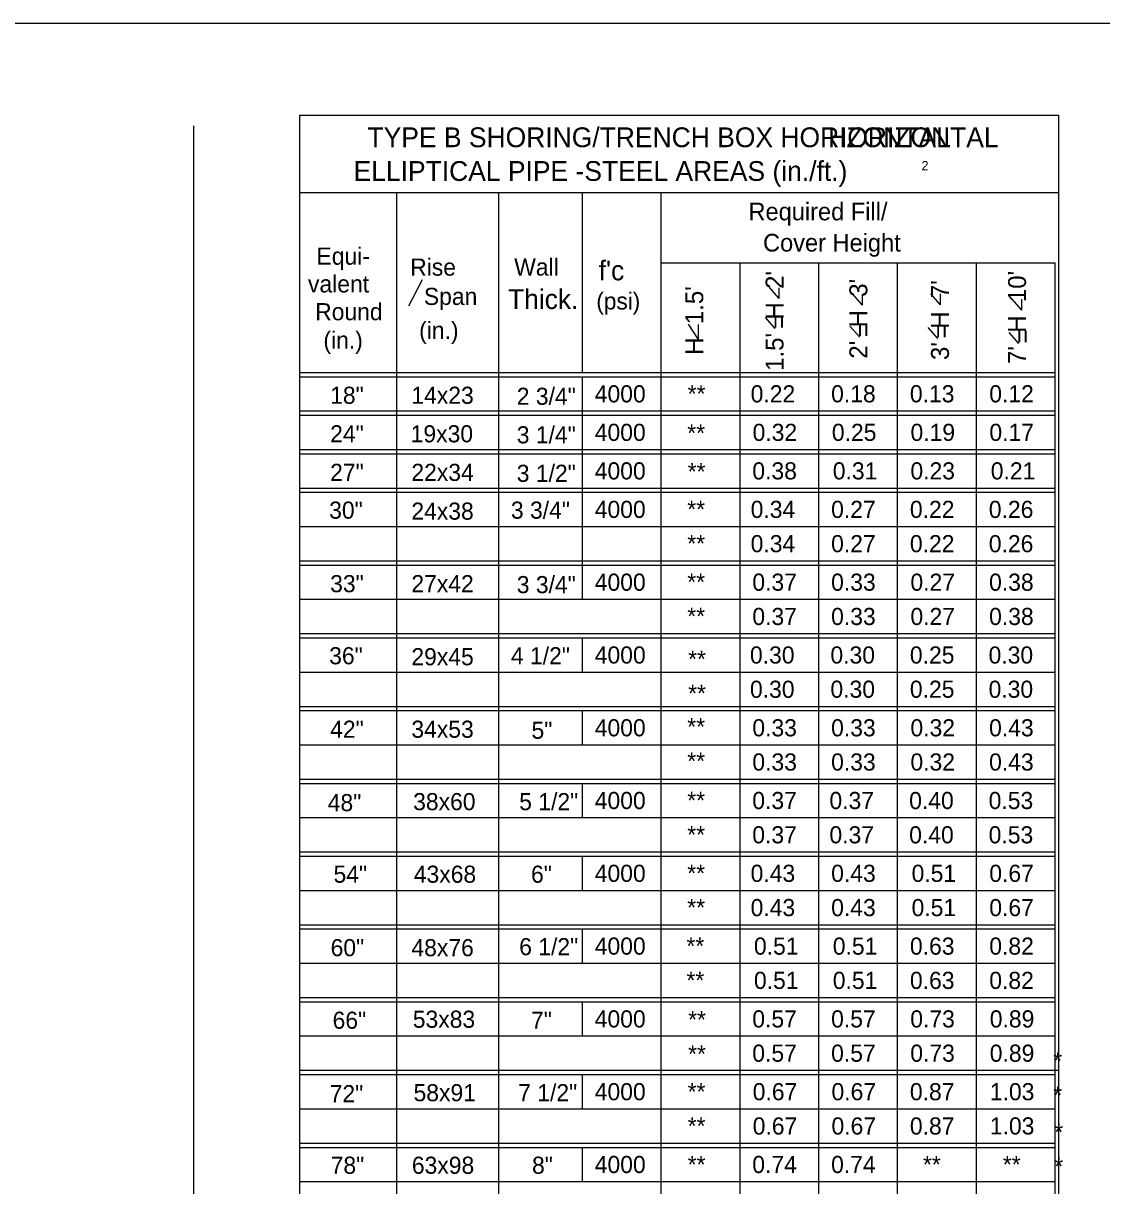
# Model space of a CAD drawing. Extents: x -22562 to -18409, y 3991 to 7171.
# Drawn here: x -19149.6 to -18976.3, y 5571.5 to 5758.4 of the extents above; entities that cross this region are included whole.
import ezdxf

# ---------------------------------------------------------------- set-up
doc = ezdxf.new("R2010")
doc.units = 0
for name, color, linetype in [('1', 7, 'Continuous'), ('2', 7, 'Continuous'), ('3', 7, 'Continuous'), ('4', 7, 'Continuous')]:
    doc.layers.add(name, color=color, linetype=linetype)

msp = doc.modelspace()

# ---------------------------------------------------------------- linework, layer by layer
at = {"layer": '1'}
for p, q in [((-19087.64, 5712.94), (-19085.45, 5717.17)), ((-19028.1, 5714.12), (-19029.67, 5715.88)), ((-19028.1, 5714.12), (-19028.1, 5715.87)), ((-19014.73, 5713.07), (-19016.29, 5714.84)), ((-19014.73, 5713.07), (-19014.73, 5714.83)), ((-19002.17, 5713.13), (-19003.73, 5714.9)), ((-19002.17, 5713.13), (-19002.17, 5714.88)), ((-18989.12, 5712.28), (-18990.68, 5714.04)), ((-18989.12, 5712.28), (-18989.12, 5714.03)), ((-19041.1, 5707.55), (-19042.67, 5709.98)), ((-19041.1, 5707.55), (-19041.1, 5709.96)), ((-19028.76, 5709.31), (-19030.32, 5711.08)), ((-19015.18, 5707.93), (-19016.75, 5709.7)), ((-19002.62, 5707.71), (-19004.18, 5709.48)), ((-18989.58, 5706.92), (-18991.14, 5708.68))]:
    msp.add_line(p, q, dxfattribs=at)
at = {"layer": '2'}
for p, q in [((-19503.85, 5758.37), (-18717.85, 5758.37)), ((-19105.2, 5743.62), (-19105.2, 5590.09)), ((-19105.2, 5743.62), (-18983.24, 5743.62)), ((-18983.23, 5743.62), (-18983.23, 5590.09)), ((-19122.26, 5741.87), (-19122.26, 5397.33)), ((-19105.2, 5731.15), (-18983.24, 5731.15)), ((-19089.62, 5731.15), (-19089.62, 5589.4)), ((-19073.24, 5731.15), (-19073.24, 5589.4)), ((-19059.78, 5731.15), (-19059.78, 5702.25)), ((-19059.77, 5731.15), (-19059.77, 5702.25)), ((-19047.12, 5731.15), (-19047.12, 5589.4)), ((-19047.12, 5719.87), (-18983.81, 5719.87)), ((-19034.45, 5719.87), (-19034.45, 5589.4)), ((-19021.79, 5719.87), (-19021.79, 5589.4)), ((-19009.13, 5719.87), (-19009.13, 5589.4)), ((-18996.46, 5719.87), (-18996.46, 5589.4)), ((-18983.81, 5719.87), (-18983.81, 5589.4)), ((-19105.2, 5702.25), (-18983.81, 5702.25)), ((-19105.2, 5701.56), (-18983.81, 5701.56)), ((-19059.77, 5701.56), (-19059.77, 5679.54)), ((-19105.2, 5696.06), (-18983.81, 5696.06)), ((-19105.2, 5696.06), (-18983.81, 5696.06)), ((-19105.2, 5695.37), (-18983.81, 5695.37)), ((-19105.2, 5695.37), (-18983.81, 5695.37)), ((-19059.77, 5695.37), (-19059.77, 5673.35)), ((-19105.2, 5689.87), (-18983.81, 5689.87)), ((-19105.2, 5689.87), (-18983.81, 5689.87)), ((-19105.2, 5689.18), (-18983.81, 5689.18)), ((-19059.77, 5689.18), (-19059.77, 5667.16)), ((-19105.2, 5683.67), (-18983.81, 5683.67)), ((-19105.2, 5683.67), (-18983.81, 5683.67)), ((-19105.2, 5683.67), (-18983.81, 5683.67)), ((-19105.2, 5682.99), (-18983.81, 5682.99)), ((-19059.77, 5682.99), (-19059.77, 5677.48)), ((-19105.2, 5677.48), (-18983.81, 5677.48)), ((-19105.2, 5671.98), (-18983.81, 5671.98)), ((-19105.2, 5671.98), (-18983.81, 5671.98)), ((-19105.2, 5671.29), (-18983.81, 5671.29)), ((-19059.77, 5671.29), (-19059.77, 5665.79)), ((-19105.2, 5665.79), (-18983.81, 5665.79)), ((-19105.2, 5660.28), (-18983.81, 5660.28)), ((-19105.2, 5660.28), (-18983.81, 5660.28)), ((-19105.2, 5659.59), (-18983.81, 5659.59)), ((-19059.77, 5659.59), (-19059.77, 5654.09)), ((-19105.2, 5654.09), (-18983.81, 5654.09)), ((-19105.2, 5648.58), (-18983.81, 5648.58)), ((-19105.2, 5648.58), (-18983.81, 5648.58)), ((-19105.2, 5647.89), (-18983.81, 5647.89)), ((-19059.77, 5647.89), (-19059.77, 5642.39)), ((-19105.2, 5642.39), (-18983.81, 5642.39)), ((-19105.2, 5636.88), (-18983.81, 5636.88)), ((-19105.2, 5636.88), (-18983.81, 5636.88)), ((-19105.2, 5636.19), (-19105.2, 5636.19)), ((-19105.2, 5636.19), (-18983.81, 5636.19)), ((-19059.77, 5636.19), (-19059.77, 5630.69)), ((-19105.2, 5630.69), (-18983.81, 5630.69)), ((-19105.2, 5625.18), (-18983.81, 5625.18)), ((-19105.2, 5625.18), (-18983.81, 5625.18)), ((-19105.2, 5624.5), (-18983.81, 5624.5)), ((-19073.24, 5624.5), (-19073.24, 5618.99)), ((-19059.77, 5624.5), (-19059.77, 5618.99)), ((-19105.2, 5618.99), (-18983.81, 5618.99)), ((-19105.2, 5613.49), (-18983.81, 5613.49)), ((-19105.2, 5613.49), (-18983.81, 5613.49)), ((-19105.2, 5612.8), (-18983.81, 5612.8)), ((-19073.24, 5612.8), (-19073.24, 5607.29)), ((-19059.77, 5612.8), (-19059.77, 5607.29)), ((-19105.2, 5607.29), (-18983.81, 5607.29)), ((-19105.2, 5601.79), (-18983.81, 5601.79)), ((-19105.2, 5601.79), (-18983.81, 5601.79)), ((-19105.2, 5601.1), (-18983.81, 5601.1)), ((-19073.24, 5601.1), (-19073.24, 5595.6)), ((-19059.77, 5601.1), (-19059.77, 5595.6)), ((-19105.2, 5595.6), (-18983.81, 5595.6)), ((-19105.2, 5590.09), (-19105.2, 5429.07)), ((-19105.2, 5590.09), (-18983.23, 5590.09)), ((-19105.2, 5590.09), (-18983.81, 5590.09)), ((-19105.2, 5590.09), (-18983.81, 5590.09)), ((-19105.2, 5589.4), (-18983.81, 5589.4)), ((-19089.62, 5589.4), (-19089.62, 5429.07)), ((-19073.24, 5589.4), (-19073.24, 5429.07)), ((-19073.24, 5589.4), (-19073.24, 5583.9)), ((-19059.77, 5589.4), (-19059.77, 5583.9)), ((-19047.12, 5589.4), (-19047.12, 5429.07)), ((-19034.45, 5589.4), (-19034.45, 5429.07)), ((-19021.79, 5589.4), (-19021.79, 5429.07)), ((-19009.13, 5589.4), (-19009.13, 5429.07)), ((-18996.46, 5589.4), (-18996.46, 5429.07)), ((-18983.81, 5589.4), (-18983.81, 5429.07)), ((-18983.23, 5590.09), (-18983.23, 5429.07)), ((-19105.2, 5583.9), (-18983.81, 5583.9)), ((-19105.2, 5578.39), (-18983.81, 5578.39)), ((-19105.2, 5578.39), (-18983.81, 5578.39)), ((-19105.2, 5577.7), (-18983.81, 5577.7)), ((-19073.24, 5577.7), (-19073.24, 5572.2)), ((-19059.77, 5577.7), (-19059.77, 5572.2)), ((-19105.2, 5572.2), (-18983.81, 5572.2))]:
    msp.add_line(p, q, dxfattribs=at)

# ---------------------------------------------------------------- texts
at = {"layer": '1'}
for s, height, p in [('HORIZONTAL', 3.178, (-19020.24, 5738.45)), ('Equi-', 2.751, (-19102.48, 5719.56)), ('Rise', 2.751, (-19087.42, 5717.8)), ('Wall', 2.751, (-19070.7, 5717.81)), ("f'c", 3.172, (-19057.13, 5717.05)), ('valent', 2.751, (-19103.84, 5715.1)), ('Span', 2.751, (-19085.22, 5713.09)), ('Thick.', 3.172, (-19071.7, 5712.44)), ('Round', 2.751, (-19102.69, 5710.63)), ('(psi)', 2.719, (-19057.51, 5712.36)), ('(in.)', 2.751, (-19085.98, 5707.64)), ('(in.)', 2.751, (-19101.37, 5706.06)), ('18"', 2.751, (-19100.28, 5697.2)), ('14x23', 2.751, (-19087.23, 5697.2)), ('2 3/4"', 2.751, (-19070.29, 5697.04)), ('24"', 2.751, (-19100.28, 5691.01)), ('19x30', 2.751, (-19087.34, 5691.01)), ('3 1/4"', 2.751, (-19070.29, 5690.85)), ('27"', 2.751, (-19100.28, 5684.81)), ('22x34', 2.751, (-19087.23, 5684.81)), ('3 1/2"', 2.751, (-19070.29, 5684.66)), ('30"', 2.751, (-19100.44, 5678.74)), ('24x38', 2.751, (-19087.23, 5678.58)), ('3 3/4"', 2.751, (-19071.23, 5678.74)), ('33"', 2.751, (-19100.28, 5666.92)), ('27x42', 2.751, (-19087.23, 5666.92)), ('3 3/4"', 2.751, (-19070.29, 5666.77)), ('36"', 2.751, (-19100.44, 5655.34)), ('29x45', 2.751, (-19087.23, 5655.18)), ('4 1/2"', 2.751, (-19071.23, 5655.34)), ('42"', 2.751, (-19100.28, 5643.53)), ('34x53', 2.751, (-19087.23, 5643.53)), ('5"', 2.751, (-19067.92, 5643.37)), ('48"', 2.751, (-19100.67, 5631.73)), ('38x60', 2.751, (-19086.94, 5631.89)), ('5 1/2"', 2.751, (-19069.9, 5631.89)), ('54"', 2.751, (-19099.74, 5620.23)), ('43x68', 2.751, (-19086.84, 5620.23)), ('6"', 2.751, (-19068, 5620.23)), ('60"', 2.751, (-19100.21, 5608.42)), ('48x76', 2.751, (-19087.22, 5608.42)), ('6 1/2"', 2.751, (-19069.9, 5608.58)), ('66"', 2.751, (-19099.89, 5596.76)), ('53x83', 2.751, (-19087, 5596.92)), ('7"', 2.751, (-19068, 5596.76)), ('72"', 2.751, (-19100.36, 5584.95)), ('58x91', 2.751, (-19086.88, 5585.11)), ('7 1/2"', 2.751, (-19070.06, 5585.11)), ('78"', 2.751, (-19100.2, 5573.45)), ('63x98', 2.751, (-19087.15, 5573.45)), ('8"', 2.751, (-19067.84, 5573.45))]:
    msp.add_text(s, height=height, dxfattribs=at).set_placement(p)
for p in [(-19026.81, 5709.28), (-19013.24, 5707.9), (-19000.67, 5707.69), (-18987.63, 5706.89)]:
    msp.add_text('=', height=2.88, rotation=90, dxfattribs=at).set_placement(p)
at = {"layer": '2'}
for s, height, p in [('2', 1.5, (-19005.24, 5734.73)), ('Required Fill/', 2.8357, (-19033.05, 5726.69)), ('Cover Height', 2.8357, (-19030.71, 5721.68))]:
    msp.add_text(s, height=height, dxfattribs=at).set_placement(p)
at = {"layer": '3'}
for s, height, p in [('**', 2.753, (-19042.82, 5697.44)), ('0.22', 2.753, (-19032.7, 5697.43)), ('0.18', 2.753, (-19019.77, 5697.44)), ('0.13', 2.753, (-19007.11, 5697.44)), ('**', 2.753, (-19042.89, 5691.13)), ('0.32', 2.753, (-19032.39, 5691.24)), ('0.25', 2.753, (-19019.65, 5691.24)), ('0.19', 2.753, (-19007.01, 5691.24)), ('0.17', 2.753, (-18994.33, 5691.24)), ('**', 2.753, (-19042.82, 5684.93)), ('0.38', 2.753, (-19032.43, 5685.05)), ('0.31', 2.753, (-19019.5, 5685.05)), ('0.23', 2.751, (-19007.02, 5685.05)), ('0.21', 2.753, (-18994.11, 5685.05)), ('**', 2.753, (-19042.89, 5678.88)), ('0.34', 2.753, (-19032.7, 5678.86)), ('0.27', 2.753, (-19019.77, 5678.86)), ('0.22', 2.753, (-19007.11, 5678.86)), ('0.34', 2.753, (-19032.7, 5673.35)), ('0.27', 2.753, (-19019.77, 5673.35)), ('0.22', 2.753, (-19007.11, 5673.35)), ('**', 2.753, (-19042.89, 5673.38)), ('**', 2.753, (-19042.89, 5667.19)), ('0.37', 2.753, (-19032.43, 5667.16)), ('0.33', 2.753, (-19019.77, 5667.16)), ('0.27', 2.751, (-19007.02, 5667.16)), ('0.38', 2.753, (-18994.38, 5667.16)), ('**', 2.753, (-19042.89, 5661.69)), ('0.37', 2.753, (-19032.43, 5661.65)), ('0.33', 2.753, (-19019.77, 5661.65)), ('0.27', 2.751, (-19007.02, 5661.65)), ('0.38', 2.753, (-18994.38, 5661.65)), ('**', 2.753, (-19042.75, 5654.8)), ('0.30', 2.753, (-19032.81, 5655.46)), ('0.30', 2.753, (-19019.88, 5655.46)), ('0.25', 2.753, (-19007.11, 5655.46)), ('**', 2.753, (-19042.75, 5649.3)), ('0.30', 2.753, (-19032.81, 5649.95)), ('0.30', 2.753, (-19019.88, 5649.96)), ('0.25', 2.753, (-19007.11, 5649.96)), ('**', 2.753, (-19042.89, 5643.93)), ('0.33', 2.753, (-19032.43, 5643.76)), ('0.33', 2.753, (-19019.77, 5643.76)), ('0.32', 2.751, (-19007.02, 5643.76)), ('0.43', 2.753, (-18994.38, 5643.76)), ('**', 2.753, (-19042.89, 5638.42)), ('0.33', 2.753, (-19032.43, 5638.26)), ('0.33', 2.753, (-19019.77, 5638.26)), ('0.32', 2.751, (-19007.02, 5638.26)), ('0.43', 2.753, (-18994.38, 5638.26)), ('**', 2.753, (-19042.89, 5632.09)), ('0.37', 2.753, (-19032.44, 5632.07)), ('0.37', 2.753, (-19020.04, 5632.07)), ('0.53', 2.753, (-18994.45, 5632.07)), ('**', 2.753, (-19042.89, 5626.58)), ('0.37', 2.753, (-19032.44, 5626.56)), ('0.37', 2.753, (-19020.04, 5626.56)), ('0.53', 2.753, (-18994.45, 5626.56)), ('**', 2.753, (-19042.89, 5620.38)), ('0.43', 2.753, (-19032.71, 5620.37)), ('0.43', 2.753, (-19019.76, 5620.37)), ('0.51', 2.753, (-19006.84, 5620.37)), ('0.67', 2.753, (-18994.35, 5620.37)), ('**', 2.753, (-19042.89, 5614.88)), ('0.43', 2.753, (-19032.71, 5614.86)), ('0.43', 2.753, (-19019.76, 5614.86)), ('0.51', 2.753, (-19006.84, 5614.86)), ('0.67', 2.753, (-18994.35, 5614.86)), ('**', 2.753, (-19043.02, 5608.69)), ('0.51', 2.753, (-19032.17, 5608.67)), ('0.51', 2.753, (-19019.5, 5608.67)), ('0.63', 2.753, (-19007.1, 5608.67)), ('0.82', 2.753, (-18994.35, 5608.67)), ('**', 2.753, (-19043.02, 5603.18)), ('0.51', 2.753, (-19032.17, 5603.16)), ('0.51', 2.753, (-19019.5, 5603.16)), ('0.63', 2.753, (-19007.1, 5603.16)), ('0.82', 2.753, (-18994.35, 5603.16)), ('**', 2.753, (-19042.75, 5596.86)), ('0.57', 2.753, (-19032.44, 5596.97)), ('0.57', 2.753, (-19019.77, 5596.97)), ('0.73', 2.753, (-19007.05, 5596.97)), ('0.89', 2.753, (-18994.27, 5596.97)), ('**', 2.753, (-19042.75, 5591.35)), ('0.57', 2.753, (-19032.44, 5591.46)), ('0.57', 2.753, (-19019.77, 5591.46)), ('0.73', 2.753, (-19007.05, 5591.46)), ('0.89', 2.753, (-18994.27, 5591.46)), ('*', 2.75, (-18984.06, 5590.24)), ('**', 2.753, (-19042.82, 5585.27)), ('0.67', 2.753, (-19032.37, 5585.27)), ('0.67', 2.753, (-19019.71, 5585.27)), ('0.87', 2.753, (-19007.11, 5585.27)), ('1.03', 2.753, (-18994.26, 5585.27)), ('*', 2.75, (-18984.06, 5584.73)), ('**', 2.753, (-19042.82, 5579.76)), ('0.67', 2.753, (-19032.37, 5579.76)), ('0.67', 2.753, (-19019.71, 5579.76)), ('0.87', 2.753, (-19007.11, 5579.76)), ('1.03', 2.753, (-18994.26, 5579.77)), ('*', 2.75, (-18983.89, 5578.78)), ('**', 2.753, (-19042.82, 5573.57)), ('0.74', 2.753, (-19032.44, 5573.57)), ('0.74', 2.753, (-19019.77, 5573.57)), ('**', 2.753, (-19005.01, 5573.57)), ('**', 2.753, (-18992.17, 5573.57)), ('*', 2.75, (-18983.89, 5573.28))]:
    msp.add_text(s, height=height, dxfattribs=at).set_placement(p)
for s, p in [('0.12', (-18994.35, 5697.43)), ('0.26', (-18994.42, 5678.85)), ('0.26', (-18994.42, 5673.34)), ('0.30', (-18994.46, 5655.45)), ('0.30', (-18994.46, 5649.95)), ('0.40', (-19007.22, 5632.06)), ('0.40', (-19007.22, 5626.55))]:
    msp.add_text(s, height=2.751, rotation=0.113, dxfattribs=at).set_placement(p)
at = {"layer": '4'}
for s, height, p in [('TYPE B SHORING/TRENCH BOX HORIZONTAL', 3.1784, (-19094.28, 5738.45)), ('ELLIPTICAL PIPE -STEEL AREAS (in./ft.)', 3.1784, (-19096.52, 5733.03)), ('4000', 2.753, (-19057.76, 5697.43)), ('4000', 2.753, (-19057.76, 5691.24)), ('4000', 2.753, (-19057.76, 5685.05)), ('4000', 2.753, (-19057.76, 5678.86)), ('4000', 2.753, (-19057.76, 5667.16)), ('4000', 2.753, (-19057.76, 5655.46)), ('4000', 2.753, (-19057.76, 5643.76)), ('4000', 2.753, (-19057.76, 5632.07)), ('4000', 2.753, (-19057.76, 5620.37)), ('4000', 2.753, (-19057.76, 5608.67)), ('4000', 2.753, (-19057.76, 5596.97)), ('4000', 2.753, (-19057.76, 5585.27)), ('4000', 2.753, (-19057.76, 5573.57))]:
    msp.add_text(s, height=height, dxfattribs=at).set_placement(p)
for s, height, p in [("1.5'  H  2'", 2.8834, (-19027.42, 5702.5)), ("7'  H  10'", 2.883, (-18988.44, 5703.6)), ("H  1.5'", 2.883, (-19040.32, 5705.08)), ("2'  H  3'", 2.883, (-19013.95, 5704.46)), ("3'  H  7'", 2.883, (-19000.83, 5704.24))]:
    msp.add_text(s, height=height, rotation=90, dxfattribs=at).set_placement(p)

doc.saveas('drawing.dxf')
